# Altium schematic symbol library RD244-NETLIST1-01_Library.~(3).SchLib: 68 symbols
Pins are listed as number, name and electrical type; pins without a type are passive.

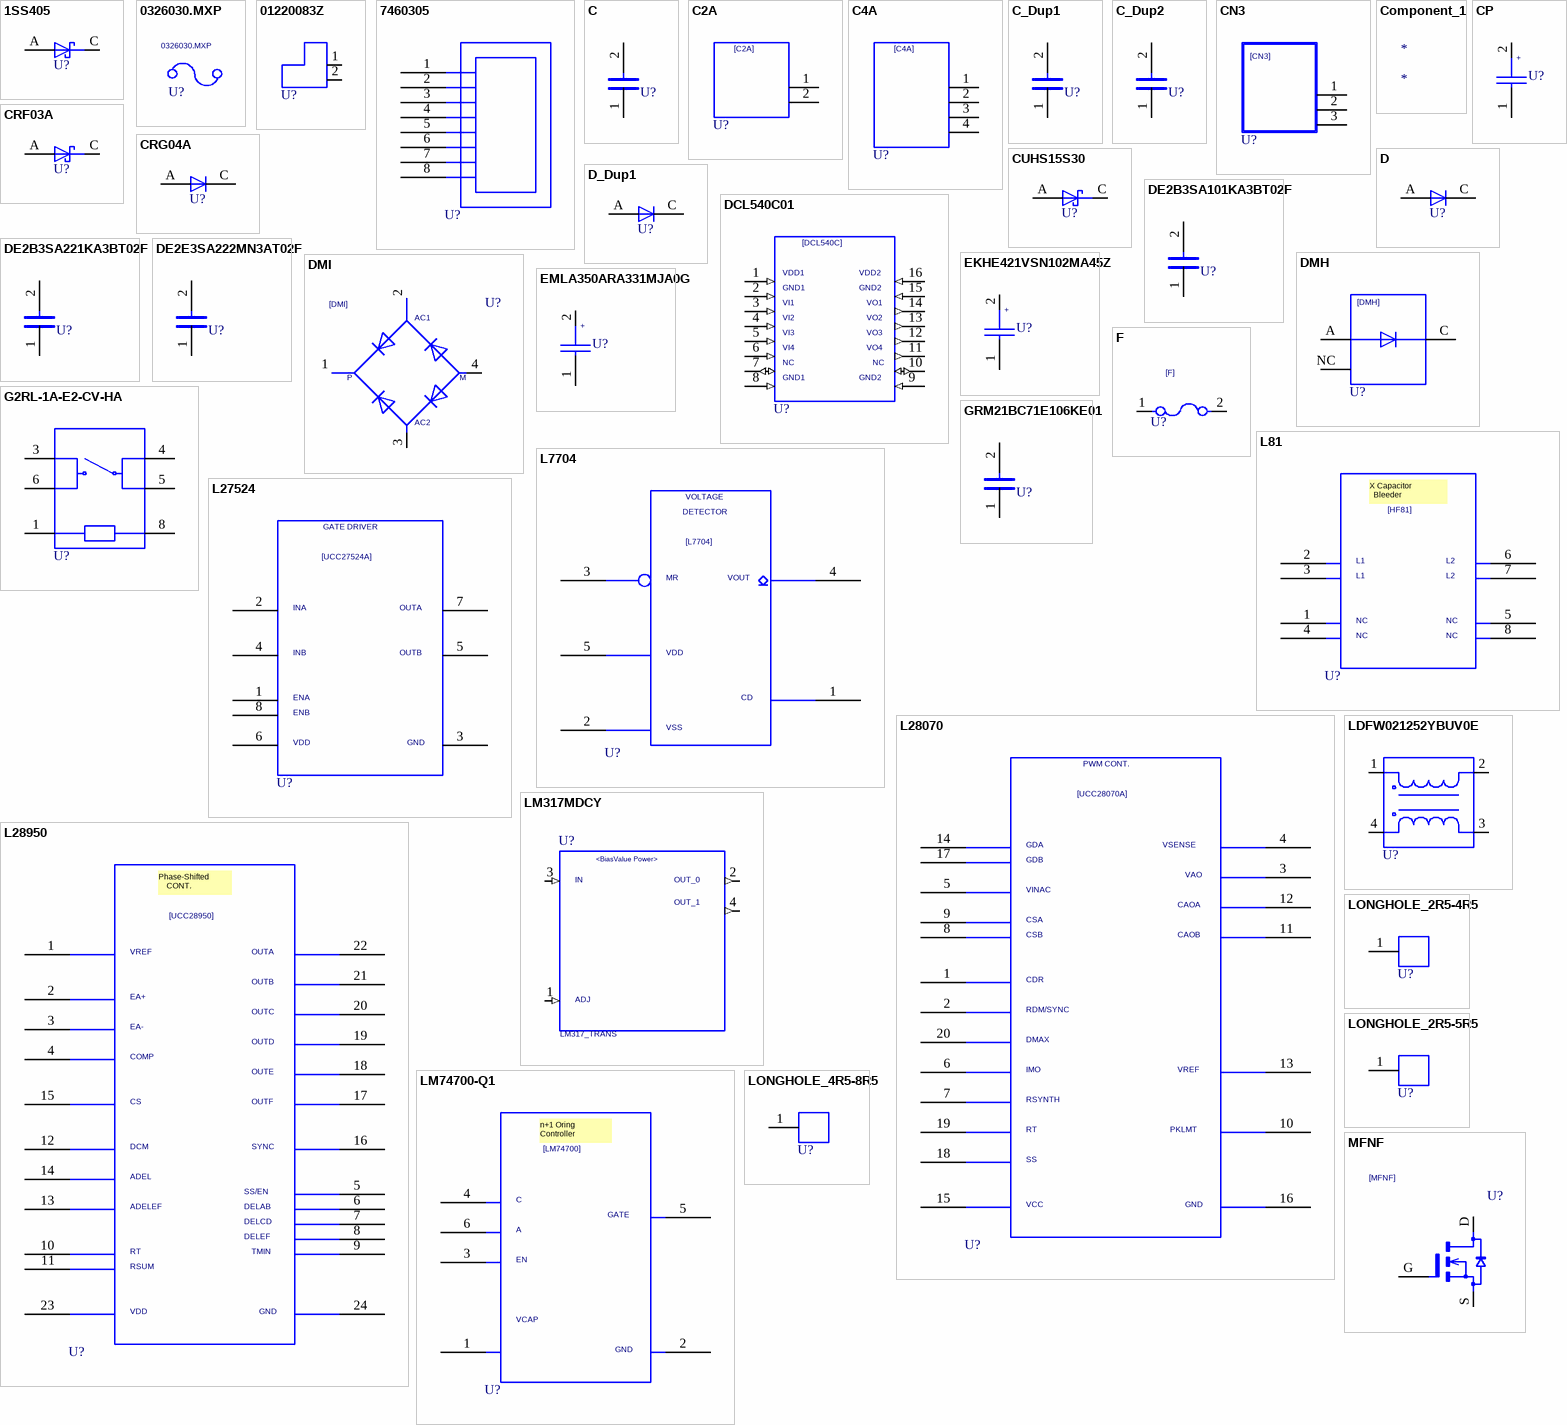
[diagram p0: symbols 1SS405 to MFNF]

## 1SS405
designator U?  (value not drawn)
SAVEAREA0: -4630,-153,17114,13055; TIME: 14:49:55; UPDATEUSER: t4887876; UPDATETIME: 11:25:22; SAVECOUNT: 16; VAL3: SOD-523; VAL1: 20V; VAL2: 0.05A; OriginalSymbolOrigin: (5080,5080); Altium-Right: 20
pins: A, C

## 0326030.MXP
designator U?  VAL3: 0326030.MXP
PCBCELLNAME: F; SAVECOUNT: 7; SAVEAREA0: -525,-4690,15446,5013; DEVICENAME: F0805B2R00FWTR; VAL1: 250VAC; VAL2: 30A SlowBlow; TIME: 10:50:48; UPDATEUSER: t4887876; UPDATETIME: 10:51:07; OriginalSymbolOrigin: (3048,3166); Altium-Right: 40; Altium-Bottom: 20

## 01220083Z
designator U?  (value not drawn)
VAL1: 250V; VAL2: 30A; TIME: 10:48:22; UPDATEUSER: t4887876; UPDATETIME: 10:49:44; SAVECOUNT: 3; OriginalSymbolOrigin: (7620,10160); Altium-Right: 30; Altium-Bottom: 40
pins: 1, 2

## 7460305
designator U?  (value not drawn)
SAVEAREA0: -4578,-286,40174,28213; SAVECOUNT: 17; TIME: 14:53:12; UPDATEUSER: t4887876; UPDATETIME: 16:00:29; VAL2: 160Amax; VAL1: M5; OriginalSymbolOrigin: (7620,27940); Altium-Right: 70; Altium-Bottom: 110
pins: 1, 2, 3, 4, 5, 6, 7, 8

## C
designator U?  (value not drawn)
OriginalSymbolOrigin: (2540,7620); Altium-Right: 20; Altium-Bottom: 10
pins: 1, 2

## C2A
designator U?  (value not drawn)
SAVEAREA0: -4611,-206,24632,18258; SAVECOUNT: 25; TIME: 13:28:28; UPDATEUSER: tomizawa-y; UPDATETIME: 12:08:31; OriginalSymbolOrigin: (2540,15240); Altium-Right: 50
pins: 1, 2

## C4A
designator U?  (value not drawn)
SAVEAREA0: -8845,-265,28754,23475; SAVECOUNT: 22; TIME: 13:28:28; UPDATEUSER: tomizawa-y; UPDATETIME: 15:03:27; OriginalSymbolOrigin: (2540,20320); Altium-Right: 50; Altium-Bottom: 70
pins: 1, 2, 3, 4

## C_Dup1
designator U?, comment C  (value not drawn)
OriginalSymbolOrigin: (2540,7620); Altium-Right: 20; Altium-Bottom: 10
pins: 1, 2

## C_Dup2
designator U?, comment C  (value not drawn)
OriginalSymbolOrigin: (2540,7620); Altium-Right: 20; Altium-Bottom: 10
pins: 1, 2

## CN3
designator U?  (value not drawn)
OriginalSymbolOrigin: (2540,17780); Altium-Right: 50; Altium-Bottom: 70
pins: 1, 2, 3

## Component_1
designator *

## CP
designator U?  (value not drawn)
SAVEAREA0: -1450,-153,20294,13055; SAVECOUNT: 52; TIME: 15:02:55; UPDATEUSER: fukuda-y; UPDATETIME: 16:13:42; OriginalSymbolOrigin: (2540,10160); Altium-Right: 20
pins: 1, 2

## CRF03A
designator U?  (value not drawn)
SAVEAREA0: -4630,-153,17114,13055; TIME: 14:49:55; UPDATEUSER: t4887876; UPDATETIME: 15:42:51; SAVECOUNT: 12; MAXV: 600V; MAXI: 0.7A; OriginalSymbolOrigin: (5080,5080); Altium-Right: 20
pins: A, C

## CRG04A
designator U?  (value not drawn)
SAVEAREA0: -4630,-153,17114,13055; TIME: 14:49:55; UPDATEUSER: t6860224; UPDATETIME: 10:39:47; SAVECOUNT: 14; MAXV: 600V; MAXI: 1A; OriginalSymbolOrigin: (5080,5080); Altium-Right: 10; Altium-Bottom: 20
pins: A, C

## CUHS15S30
designator U?  (value not drawn)
SAVEAREA0: -4630,-153,17114,13055; TIME: 14:49:55; UPDATEUSER: t4887876; UPDATETIME: 17:19:09; SAVECOUNT: 10; OriginalSymbolOrigin: (5080,5080); Altium-Right: 20
pins: A, C

## D
designator U?  (value not drawn)
SAVEAREA0: -225,-91,12804,7836; SAVECOUNT: 3; TIME: 14:49:55; UPDATEUSER: 19870035; UPDATETIME: 14:20:16; OriginalSymbolOrigin: (5080,5080); Altium-Right: 10; Altium-Bottom: 20
pins: A, C

## D_Dup1
designator U?, comment D  (value not drawn)
SAVEAREA0: -225,-91,12804,7836; SAVECOUNT: 3; TIME: 14:49:55; UPDATEUSER: 19870035; UPDATETIME: 14:20:16; OriginalSymbolOrigin: (5080,5080); Altium-Right: 10; Altium-Bottom: 20
pins: A, C

## DCL540C01
designator U?  (value not drawn)
TIME: 11:12:35; UPDATEUSER: t6860224; UPDATETIME: 18:45:42; SAVECOUNT: 6; SAVEAREA0: -81052,-32740,106905,52903; OriginalSymbolOrigin: (5080,27940); Altium-Right: 80; Altium-Bottom: 110
pins: 1 (in), 2 (in), 3 (in), 4 (in), 5 (in), 6 (in), 7 (io), 8 (in), 9 (in), 10 (io), 11 (out), 12 (out), 13 (out), 14 (out), 15 (in), 16 (in)

## DE2B3SA101KA3BT02F
designator U?  (value not drawn)
VAL1: 100pF; VAL2: 250V; TIME: 18:06:52; UPDATEUSER: t6860224; SAVECOUNT: 1; OriginalSymbolOrigin: (2540,7620); Altium-Right: 20; Altium-Bottom: 10
pins: 1, 2

## DE2B3SA221KA3BT02F
designator U?  (value not drawn)
VAL1: 220pF(K); VAL2: 250V; TIME: 18:06:26; UPDATEUSER: t6860224; SAVECOUNT: 1; OriginalSymbolOrigin: (2540,7620); Altium-Right: 20; Altium-Bottom: 10
pins: 1, 2

## DE2E3SA222MN3AT02F
designator U?  (value not drawn)
VAL1: 2.2nF(M); VAL2: 250V; TIME: 18:04:40; UPDATEUSER: t6860224; UPDATETIME: 18:05:46; SAVECOUNT: 2; OriginalSymbolOrigin: (2540,7620); Altium-Right: 20; Altium-Bottom: 10
pins: 1, 2

## DMH
designator U?  (value not drawn)
SAVEAREA0: -4931,-287,27399,20979; TIME: 08:58:08; UPDATEUSER: kishi-s; UPDATETIME: 09:01:52; SAVECOUNT: 2; OriginalSymbolOrigin: (5080,17780); Altium-Right: 50; Altium-Bottom: 60
pins: A, C, NC

## DMI
designator U?  (value not drawn)
SAVECOUNT: 7; SAVEAREA0: -7762,-358,32649,26224; TIME: 10:09:47; UPDATEUSER: fukuda-y; UPDATETIME: 17:30:39; OriginalSymbolOrigin: (0,25400); Altium-Right: 90
pins: 1, 2, 3, 4

## EKHE421VSN102MA45Z
designator U?  (value not drawn)
SAVEAREA0: -1450,-153,20294,13055; SAVECOUNT: 53; TIME: 15:02:55; UPDATEUSER: t4887876; UPDATETIME: 08:41:08; VAL1: 420V; VAL2: 1010uF(M); OriginalSymbolOrigin: (2540,10160); Altium-Right: 20
pins: 1, 2

## EMLA350ARA331MJA0G
designator U?  (value not drawn)
SAVEAREA0: -1450,-153,20294,13055; SAVECOUNT: 53; TIME: 15:02:55; UPDATEUSER: t6860224; UPDATETIME: 18:00:37; VAL1: 330uF(M); VAL2: 35V; OriginalSymbolOrigin: (2540,10160); Altium-Right: 20
pins: 1, 2

## F
designator U?  (value not drawn)
OriginalSymbolOrigin: (2540,5080); Altium-Right: 40; Altium-Bottom: 20
pins: 1, 2

## G2RL-1A-E2-CV-HA
designator U?  (value not drawn)
TIME: 17:19:14; UPDATEUSER: t4887876; UPDATETIME: 19:21:58; SAVECOUNT: 7; COMP: G2RL-1A-E2-CV-HA_DC12; OriginalSymbolOrigin: (5080,20320); Altium-Right: 60; Altium-Bottom: 80
pins: 1, 3, 4, 5, 6, 8

## GRM21BC71E106KE01
designator U?  (value not drawn)
TIME: 10:25:11; UPDATEUSER: t4887876; UPDATETIME: 16:23:00; SAVECOUNT: 11; VAL1: 10uF(K); VAL2: 25V; MAKER: Murata; CHIPSET: 2012; OriginalSymbolOrigin: (2540,7620); Altium-Right: 20; Altium-Bottom: 10
pins: 1, 2

## L81
designator U?  (value not drawn)
SAVEAREA0: -12429,-3512,55842,41521; TIME: 18:31:00; UPDATEUSER: cae; UPDATETIME: 11:10:50; SAVECOUNT: 13; OriginalSymbolOrigin: (7620,35560); Altium-Right: 110; Altium-Bottom: 130
pins: 1, 2, 3, 4, 5, 6, 7, 8

## L7704
designator U?  (value not drawn)
SAVECOUNT: 23; SAVEAREA0: -14253,-557,65080,48696; TIME: 18:10:57; UPDATEUSER: 19990028; UPDATETIME: 10:41:32; OriginalSymbolOrigin: (7620,45720); Altium-Right: 140; Altium-Bottom: 170
pins: 1, 2, 3, 4, 5

## L27524
designator U?  (value not drawn)
SAVEAREA0: -24347,-591,50370,48694; SAVECOUNT: 22; TIME: 15:02:55; UPDATEUSER: cae; UPDATETIME: 14:54:38; OriginalSymbolOrigin: (7620,45720); Altium-Right: 110; Altium-Bottom: 170
pins: 1, 2, 3, 4, 5, 6, 7, 8

## L28070
designator U?  (value not drawn)
SAVEAREA0: -12344,-1037,78634,87348; SAVECOUNT: 29; TIME: 15:02:55; UPDATEUSER: cae; UPDATETIME: 14:36:12; OriginalSymbolOrigin: (7620,83820); Altium-Right: 200; Altium-Bottom: 320
pins: 1, 2, 3, 4, 5, 6, 7, 8, 9, 10, 11, 12, 13, 14, 15, 16, 17, 18, 19, 20

## L28950
designator U?  (value not drawn)
SAVEAREA0: -25263,1478,86635,87004; SAVECOUNT: 35; TIME: 15:02:55; UPDATEUSER: cae; UPDATETIME: 16:32:09; OriginalSymbolOrigin: (7620,83820); Altium-Right: 180; Altium-Bottom: 320
pins: 1, 2, 3, 4, 5, 6, 7, 8, 9, 10, 11, 12, 13, 14, 15, 16, 17, 18, 19, 20, 21, 22, 23, 24

## LDFW021252YBUV0E
designator U?  (value not drawn)
DEVICENAME: DLW21HN670SQ2; SAVEAREA0: -21350,-26515,41553,39372; TIME: 11:39:40; UPDATEUSER: t4887876; UPDATETIME: 20:09:21; SAVECOUNT: 7; VAL1: 8.1mH; VAL2: 21A; OriginalSymbolOrigin: (2540,12700); Altium-Right: 60
pins: 1 (io), 2 (io), 3 (io), 4 (io)

## LM317MDCY
designator U?, comment LM317_TRANS
ALTERNATE PARTNUMBER: LM317DCY; PARTNUMBER: LM317DCYR; MANUFACTURER: Texas Instruments; PIN_COUNT: 4; SYMBOLCREATER: Altium; DEVICESINPACKAGE: 1; COMP: LM317MDCY; ISHETEROGENEOUS: False; DEVICEDESIGNATOR: A; DEVICENUMBERING: Alpha; PSPICETEMPLATE: X^@REFDES %IN %ADJ %OUT_0 %OUT_1 @MODEL; ORIGINALSYMBOLORIGIN: (2540,30480); COMPTYPE: IC; TIME: 16:40:05; UPDATEUSER: t6860224; UPDATETIME: 16:01:55; SAVECOUNT: 6; SAVEAREA0: -16909,0,49982,30480; Altium-Right: 110; Altium-Bottom: 120
simulation model LM317MDCY
pins: 1 (in), 2 (out), 3 (in), 4 (out)

## LM74700-Q1
designator U?  (value not drawn)
SAVEAREA0: -16399,-622,62276,51274; TIME: 11:49:52; UPDATEUSER: t4887876; UPDATETIME: 18:16:17; SAVECOUNT: 39; OriginalSymbolOrigin: (7620,48260); Altium-Right: 120; Altium-Bottom: 180
pins: 1, 2, 3, 4, 5, 6

## LONGHOLE_2R5-4R5
designator U?, comment Longhole_2R5-4R5  (value not drawn)
TIME: 17:17:39; UPDATEUSER: t4887876; UPDATETIME: 09:28:53; SAVECOUNT: 11; VAL3: PCB Pad; OriginalSymbolOrigin: (5080,5080); Altium-Right: 20
pins: 1

## LONGHOLE_2R5-5R5
designator U?, comment Longhole_2R5-5R5  (value not drawn)
TIME: 17:17:39; UPDATEUSER: t4887876; UPDATETIME: 09:28:53; SAVECOUNT: 11; VAL3: PCB Pad; OriginalSymbolOrigin: (5080,5080); Altium-Right: 20
pins: 1

## LONGHOLE_4R5-8R5
designator U?, comment Longhole_4R5-8R5  (value not drawn)
TIME: 17:17:39; UPDATEUSER: t4887876; UPDATETIME: 09:28:53; SAVECOUNT: 12; VAL3: PCB Pad; OriginalSymbolOrigin: (5080,5080); Altium-Right: 20
pins: 1

## MFNF
designator U?  (value not drawn)
SAVECOUNT: 11; SAVEAREA0: -7027,-292,21786,15988; OriginalSymbolOrigin: (5080,12700); Altium-Right: 40
pins: D, G, S

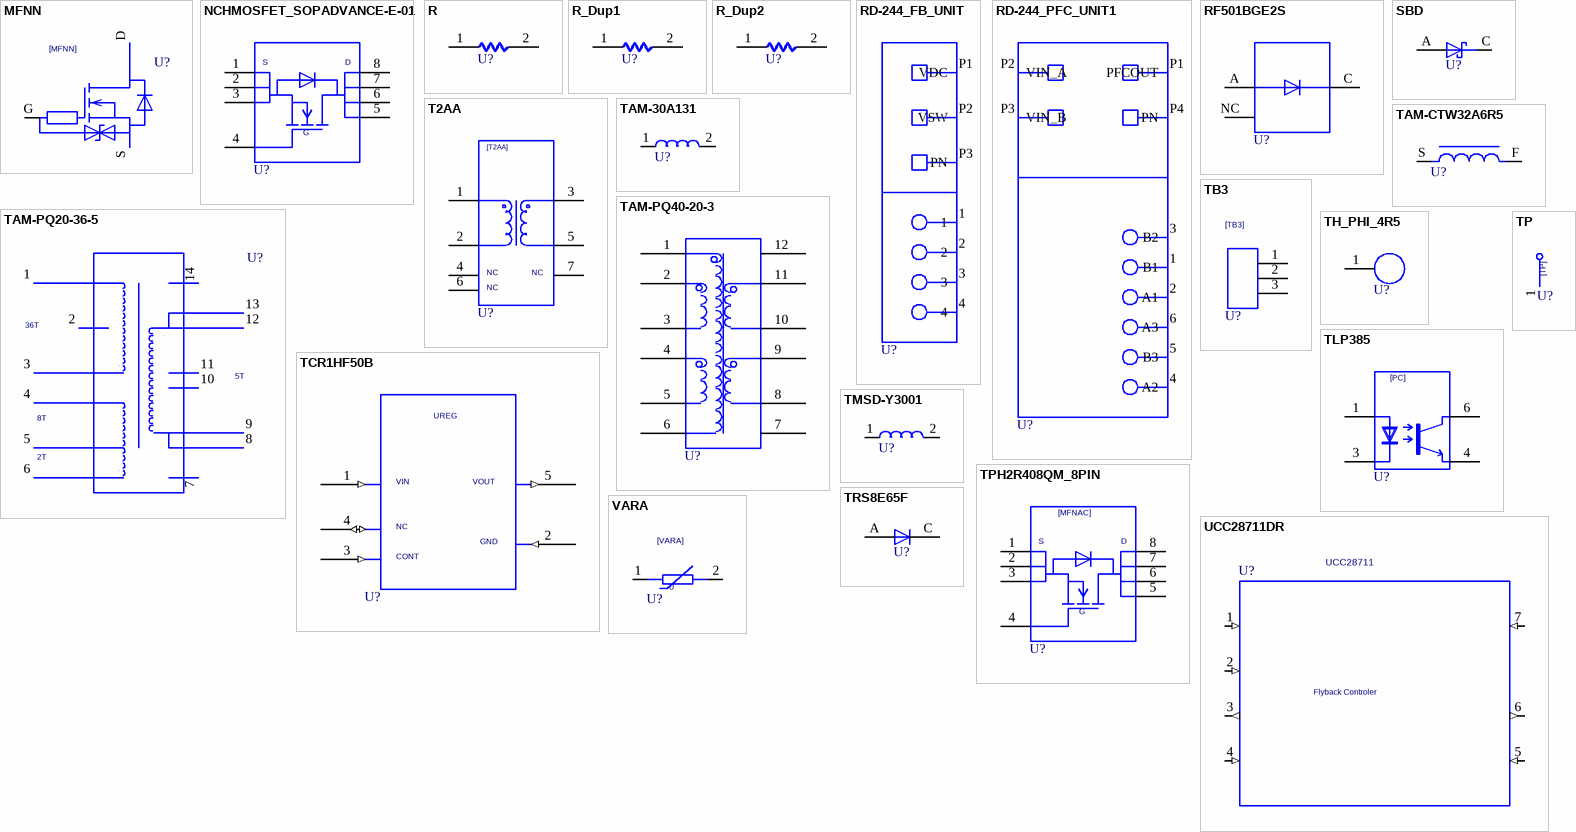
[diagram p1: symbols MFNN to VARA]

## MFNN
designator U?  (value not drawn)
SAVECOUNT: 25; SAVEAREA0: -2884,-274,25430,18334; TIME: 08:01:03; UPDATEUSER: sato-yr; UPDATETIME: 13:42:20; OriginalSymbolOrigin: (2540,17780); Altium-Right: 80; Altium-Bottom: 70
pins: D, G, S

## NCHMOSFET_SOPADVANCE-E-01
designator U?  (value not drawn)
TIME: 18:29:30; UPDATEUSER: t4887876; UPDATETIME: 14:15:50; SAVECOUNT: 31; SAVEAREA0: -10143,-336,37609,28718; COMP: NchMOSFET_SOPAdvance(E)-01; VAL3: ※型名を記入する(SOPAdvance(E)); VAL1: ※定格電圧を記入する; VAL2: ※定格電流を記入する; CHIPSET: ※型名を記入する; OriginalSymbolOrigin: (5080,22860); Altium-Right: 70; Altium-Bottom: 80
pins: 1, 2, 3, 4, 5, 6, 7, 8

## R
designator U?  (value not drawn)
OriginalSymbolOrigin: (5080,5080); Altium-Right: 20
pins: 1, 2

## R_Dup1
designator U?, comment R  (value not drawn)
OriginalSymbolOrigin: (5080,5080); Altium-Right: 20
pins: 1, 2

## R_Dup2
designator U?, comment R  (value not drawn)
OriginalSymbolOrigin: (5080,5080); Altium-Right: 20
pins: 1, 2

## RD-244_FB_UNIT
designator U?, comment RD-244_FB_Unit  (value not drawn)
TIME: 11:34:46; UPDATEUSER: t4887876; UPDATETIME: 08:09:20; SAVECOUNT: 38; SAVEAREA0: -20981,-344,43891,33349; VAL3: 3305-1-15-80-47-27-10-0 : 4pcs実装; OriginalSymbolOrigin: (0,50800); Altium-Right: 50; Altium-Bottom: 200
pins: 1, 2, 3, 4, P1 VDC, P2 VSW, P3 PN

## RD-244_PFC_UNIT1
designator U?  (value not drawn)
TIME: 11:34:46; UPDATEUSER: t5459927; UPDATETIME: 16:41:12; SAVECOUNT: 29; SAVEAREA0: -20981,-344,43891,33349; VAL3: 3305-1-15-80-47-27-10-0 : 6pcs実装; OriginalSymbolOrigin: (0,63500); Altium-Right: 100; Altium-Bottom: 250
pins: 1 B1, 2 A1, 3 B2, 4 A2, 5 B3, 6 A3, P1 PFCOUT, P2 VIN_A, P3 VIN_B, P4 PN

## RF501BGE2S
designator U?  (value not drawn)
SAVEAREA0: -4931,-287,27399,20979; TIME: 08:58:08; UPDATEUSER: t4887876; UPDATETIME: 11:52:14; SAVECOUNT: 7; VAL1: 200V; VAL2: 5A; CHIPSET: TO-252GE; OriginalSymbolOrigin: (5080,17780); Altium-Right: 50; Altium-Bottom: 60
pins: A, C, NC

## SBD
designator U?  (value not drawn)
SAVEAREA0: -4630,-153,17114,13055; TIME: 14:49:55; UPDATEUSER: fukuda-y; UPDATETIME: 08:16:22; SAVECOUNT: 9; OriginalSymbolOrigin: (5080,5080); Altium-Right: 20
pins: A, C

## T2AA
designator U?  (value not drawn)
TIME: 11:34:46; UPDATEUSER: t4887876; UPDATETIME: 16:34:34; SAVECOUNT: 11; SAVEAREA0: -20981,-344,43891,33349; OriginalSymbolOrigin: (5080,30480); Altium-Right: 50; Altium-Bottom: 110
pins: 1, 2, 3, 4, 5, 6, 7

## TAM-30A131
designator U?  (value not drawn)
VAL1: 100uH min.; VAL2: 30A; TIME: 14:26:02; UPDATEUSER: t4887876; SAVECOUNT: 1; OriginalSymbolOrigin: (2540,5080); Altium-Right: 30; Altium-Bottom: 20
pins: 1, 2

## TAM-CTW32A6R5
designator U?  (value not drawn)
SAVECOUNT: 8; SAVEAREA0: -384,-828,17939,11225; TIME: 16:55:46; UPDATEUSER: t4887876; UPDATETIME: 06:59:32; VAL1: 9.5uH; VAL2: 32A; MAKER: TAMURA; OriginalSymbolOrigin: (2540,5080); Altium-Right: 50; Altium-Bottom: 20
pins: F, S

## TAM-PQ20-36-5
designator U?, comment T3_12V67A  (value not drawn)
UPDATEUSER: t4887876; COMP: TAM-PQ20-36-5; UPDATETIME: 19:22:14; SAVECOUNT: 16; TIME: 16:40:06; SAVEAREA0: -85659,-25353,110804,64166; ORIGINALSYMBOLORIGIN: (0,40640); VAL1: 36:8:2:5; Altium-Right: 140; Altium-Bottom: 160
pins: 1, 2, 3, 4, 5, 6, 7, 8, 9, 10, 11, 12, 13, 14

## TAM-PQ40-20-3
designator U?, comment T3_12V67A  (value not drawn)
UPDATEUSER: t4887876; COMP: TAM-PQ40-20-3; UPDATETIME: 20:17:22; SAVECOUNT: 8; TIME: 16:40:06; SAVEAREA0: -9901,-21944,29587,7006; ORIGINALSYMBOLORIGIN: (0,0); Altium-Right: 50; Altium-Bottom: 140
pins: 1, 2, 3, 4, 5, 6, 7, 8, 9, 10, 11, 12

## TB3
designator U?  (value not drawn)
SAVEAREA0: -8260,-205,20967,17940; TIME: 13:41:39; UPDATEUSER: 19990028; UPDATETIME: 11:31:50; SAVECOUNT: 4; OriginalSymbolOrigin: (2540,12700); Altium-Right: 20; Altium-Bottom: 40
pins: 1, 2, 3

## TCR1HF50B
designator U?  (value not drawn)
SAVEAREA0: -444,-3509,43701,41525; TIME: 18:31:00; UPDATEUSER: t6860224; UPDATETIME: 18:26:20; SAVECOUNT: 21; VAL1: Linear Regulator; OriginalSymbolOrigin: (7620,35560); Altium-Right: 110; Altium-Bottom: 130
pins: 1 (in), 2 (in), 3 (in), 4 (io), 5 (out)

## TH_PHI_4R5
designator U?, comment TH_phi_4R5  (value not drawn)
TIME: 17:17:39; UPDATEUSER: t4887876; UPDATETIME: 10:35:58; SAVECOUNT: 11; VAL3: PCB Pad; OriginalSymbolOrigin: (5080,5080); Altium-Right: 20
pins: 1

## TLP385
designator U?  (value not drawn)
TIME: 18:37:26; UPDATEUSER: t4887876; UPDATETIME: 18:41:04; SAVECOUNT: 3; VAL3: TLP385(D4BLLTL,E; OriginalSymbolOrigin: (5080,17780); Altium-Right: 50; Altium-Bottom: 70
pins: 1, 3, 4, 6

## TMSD-Y3001
designator U?  (value not drawn)
VAL1: 13uH; TIME: 11:29:15; UPDATEUSER: t4887876; UPDATETIME: 13:47:51; SAVECOUNT: 2; OriginalSymbolOrigin: (2540,5080); Altium-Right: 30; Altium-Bottom: 20
pins: 1, 2

## TP
designator U?  (value not drawn)
TIME: 16:12:21; UPDATEUSER: fukuda-y; UPDATETIME: 16:18:11; SAVECOUNT: 2; SAVEAREA0: -242,-92,12810,7836; OriginalSymbolOrigin: (0,7620); Altium-Right: 20; Altium-Bottom: 30
pins: 1

## TPH2R408QM_8PIN
designator U?  (value not drawn)
TIME: 18:29:30; UPDATEUSER: t4887876; UPDATETIME: 15:52:00; SAVECOUNT: 28; SAVEAREA0: -10143,-336,37609,28718; COMP: TPH2R408QM(L1Q); VAL1: 80V; VAL2: 120A; OriginalSymbolOrigin: (5080,25400); Altium-Right: 70; Altium-Bottom: 90
pins: 1, 2, 3, 4, 5, 6, 7, 8

## TRS8E65F
designator U?  (value not drawn)
SAVEAREA0: -225,-91,12804,7836; SAVECOUNT: 5; TIME: 14:49:55; UPDATEUSER: t6860224; UPDATETIME: 17:57:03; VAL3: TRS8E65H; OriginalSymbolOrigin: (5080,5080); Altium-Right: 10; Altium-Bottom: 20
pins: A, C

## UCC28711DR
designator U?, comment UCC28711
COMP: UCC28711DR; PSPICETEMPLATE: X^@REFDES %CS %VS %CBC %DRV %VDD %GND %HV @MODEL; TIME: 16:40:05; UPDATEUSER: t4887876; UPDATETIME: 09:12:44; SAVECOUNT: 14; SAVEAREA0: -40606,-13411,99691,50516; OriginalSymbolOrigin: (2540,38100); Altium-Right: 180; Altium-Bottom: 150
simulation model UCC28711DR
pins: 1 (in), 2 (in), 3 (out), 4 (in), 5 (in), 6 (out), 7 (in)

## VARA
designator U?  (value not drawn)
SAVEAREA0: -9950,-8554,25168,13619; SAVECOUNT: 12; TIME: 09:56:50; UPDATEUSER: tomizawa-y; OriginalSymbolOrigin: (2540,5080); Altium-Right: 40; Altium-Bottom: 20
pins: 1, 2

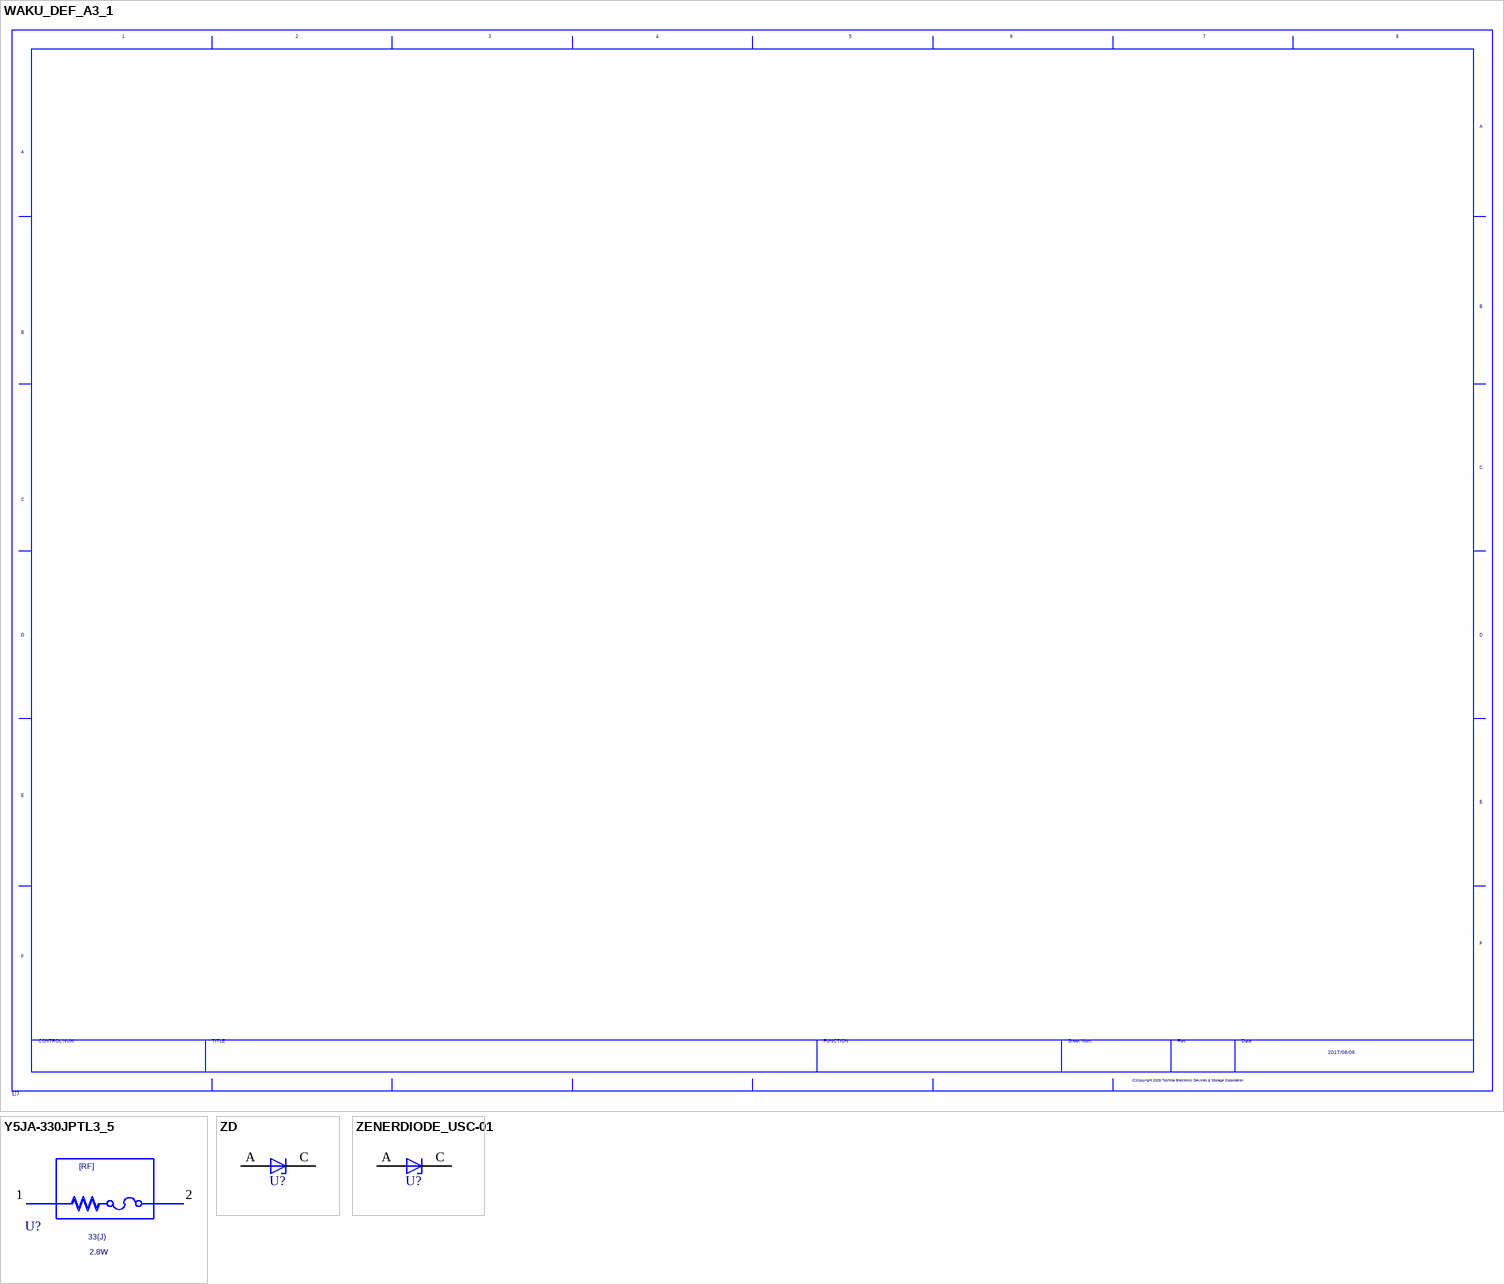
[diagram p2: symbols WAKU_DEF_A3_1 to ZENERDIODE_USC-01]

## WAKU_DEF_A3_1
designator U?  DATE: 2017/06/06  (hidden comment: WAKU_DEF_A3_1)
PLOTTIME: HH:MM; SAVEAREA0: 96913,-567914,509243,-368858; TIME: 14:30:25; UPDATEUSER: HP_Z8_KEYSHOT; UPDATETIME: 14:29:25; SAVECOUNT: 22; ZONEOFFSETX: 36; ZONEOFFSETY: -24; OriginalSymbolOrigin: (12700,-12700); Altium-Right: 2300; Altium-Bottom: 1650

## Y5JA-330JPTL3_5
designator U?  VAL1: 33(J)  VAL2: 2.8W  (hidden comment: Y5JA-330JPTL3_5)
VAL3: Y5JA-330JPTL3.5; TIME: 16:26:39; UPDATEUSER: t4887876; UPDATETIME: 20:40:35; SAVECOUNT: 5; OriginalSymbolOrigin: (-1270,12700); Altium-Right: 110; Altium-Bottom: 40
pins: 1, 2

## ZD
designator U?  (value not drawn)
SAVEAREA0: -4630,-153,17114,13055; TIME: 14:49:55; UPDATEUSER: fukuda-y; UPDATETIME: 08:18:42; SAVECOUNT: 6; OriginalSymbolOrigin: (5080,5080); Altium-Right: 10; Altium-Bottom: 20
pins: A, C

## ZENERDIODE_USC-01
designator U?, comment ZenerDiode_USC-01  (value not drawn)
SAVEAREA0: -4630,-153,17114,13055; TIME: 14:49:55; UPDATEUSER: t4887876; UPDATETIME: 08:23:49; SAVECOUNT: 9; OriginalSymbolOrigin: (5080,5080); Altium-Right: 10; Altium-Bottom: 20
pins: A, C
